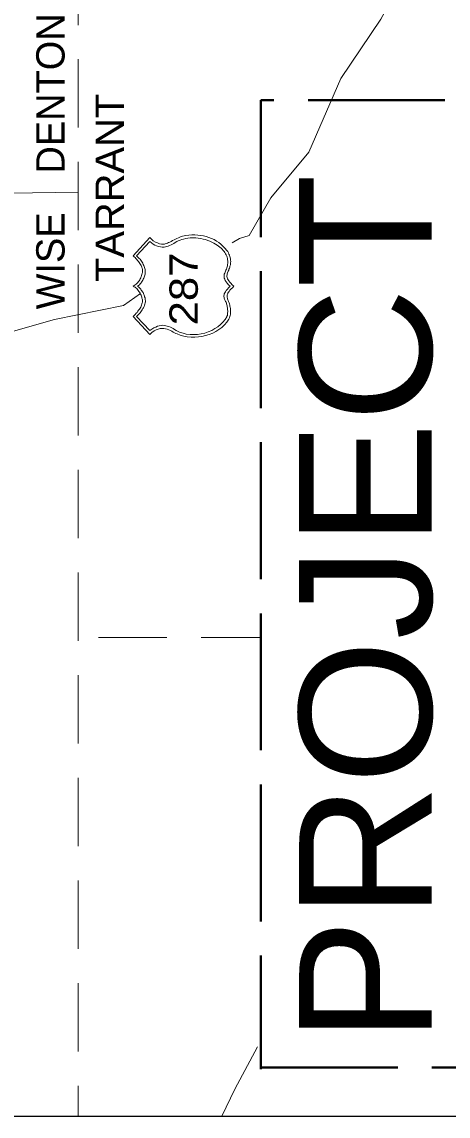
# Model space of a CAD drawing. Extents: x 2363323 to 2367082, y 6956018 to 6980837.
# Drawn here: x 2365838.7 to 2365915.4, y 6980386 to 6980582.6 of the extents above; entities that cross this region are included whole.
import ezdxf

# ---------------------------------------------------------------- set-up
doc = ezdxf.new("R2010")
doc.units = 0
doc.header["$LTSCALE"] = 4.1
doc.linetypes.add('LONG_DASHED', pattern=[7.5, 6, -1.5])
doc.linetypes.add('MEDIUM_DASHED', pattern=[4.5, 3, -1.5])
doc.layers.add('62', color=7, linetype='Continuous', lineweight=13)
doc.layers.add('63', color=7, linetype='Continuous', lineweight=13)

msp = doc.modelspace()

# ---------------------------------------------------------------- linework, layer by layer
at = {"layer": '62', "linetype": 'MEDIUM_DASHED'}
for p, q in [((2365848.822, 6980834.218), (2365848.821, 6980385.954)), ((2365848.822, 6980551.996), (2365753.976, 6980551.008)), ((2365852.512, 6980472.003), (2365881.718, 6980472.003))]:
    msp.add_line(p, q, dxfattribs=at)
at = {"layer": '62'}
for p, q in [((2365877.872, 6980543.694), (2365876.544, 6980542.906)), ((2365856.966, 6980531.656), (2365860.026, 6980533.816)), ((2365877.039, 6980390.817), (2365881.089, 6980398.377)), ((2365874.678, 6980385.954), (2365877.039, 6980390.817))]:
    msp.add_line(p, q, dxfattribs=at)
at = {"layer": '62', "lineweight": 25}
msp.add_lwpolyline([(2365753.976, 6980385.954), (2366219.249, 6980385.954), (2366219.249, 6980835.546), (2365753.974, 6980835.546)], dxfattribs=at)
at = {"layer": '62'}
for points in [[(2365877.872, 6980543.694), (2365879.582, 6980544.234), (2365883.498, 6980551.006), (2365890.316, 6980559.222), (2365896.098, 6980572.431), (2365903.3, 6980583.117), (2365906.968, 6980589.936)], [(2365861.714, 6980526.435), (2365858.698, 6980529.699), (2365858.902, 6980529.878), (2365859.104, 6980530.059), (2365859.262, 6980530.263), (2365859.441, 6980530.418), (2365859.574, 6980530.622), (2365859.711, 6980530.802), (2365859.846, 6980530.982), (2365859.981, 6980531.184), (2365860.094, 6980531.343), (2365860.161, 6980531.546), (2365860.251, 6980531.722), (2365860.296, 6980531.926), (2365860.364, 6980532.106), (2365860.408, 6980532.264), (2365860.408, 6980532.489), (2365860.386, 6980532.692), (2365860.364, 6980532.826), (2365860.296, 6980532.986), (2365860.275, 6980533.166), (2365860.23, 6980533.344), (2365860.138, 6980533.522), (2365860.071, 6980533.682), (2365859.981, 6980533.862), (2365859.891, 6980534.042), (2365859.756, 6980534.199), (2365859.644, 6980534.379), (2365859.488, 6980534.538), (2365859.374, 6980534.696), (2365859.216, 6980534.806), (2365859.06, 6980534.943), (2365858.878, 6980535.01), (2365858.698, 6980535.12), (2365858.878, 6980535.234), (2365859.06, 6980535.345), (2365859.238, 6980535.482), (2365859.374, 6980535.616), (2365859.554, 6980535.774), (2365859.666, 6980535.952), (2365859.802, 6980536.112), (2365859.914, 6980536.293), (2365860.004, 6980536.472), (2365860.118, 6980536.629), (2365860.184, 6980536.854), (2365860.251, 6980537.01), (2365860.296, 6980537.259), (2365860.365, 6980537.416), (2365860.408, 6980537.642), (2365860.408, 6980537.822), (2365860.41, 6980537.979), (2365860.41, 6980538.182), (2365860.341, 6980538.316), (2365860.296, 6980538.519), (2365860.206, 6980538.699), (2365860.14, 6980538.856), (2365860.026, 6980539.014), (2365859.914, 6980539.216), (2365859.801, 6980539.374), (2365859.666, 6980539.554), (2365859.532, 6980539.713), (2365859.374, 6980539.914), (2365859.216, 6980540.072), (2365859.058, 6980540.252), (2365858.878, 6980540.408), (2365858.698, 6980540.589), (2365861.714, 6980543.852), (2365862.008, 6980543.558), (2365862.345, 6980543.265), (2365862.726, 6980543.064), (2365863.107, 6980542.908), (2365863.491, 6980542.749), (2365863.851, 6980542.683), (2365864.144, 6980542.682), (2365864.346, 6980542.682), (2365864.504, 6980542.726), (2365864.708, 6980542.794), (2365864.886, 6980542.862), (2365865.112, 6980542.952), (2365865.338, 6980543.062), (2365865.561, 6980543.176), (2365865.808, 6980543.313), (2365866.078, 6980543.446), (2365866.328, 6980543.582), (2365866.575, 6980543.716), (2365866.866, 6980543.829), (2365867.114, 6980543.942), (2365867.384, 6980544.033), (2365867.631, 6980544.122), (2365867.88, 6980544.189), (2365868.126, 6980544.234), (2365868.711, 6980544.302), (2365869.274, 6980544.369), (2365869.792, 6980544.369), (2365870.334, 6980544.302), (2365870.853, 6980544.258), (2365871.369, 6980544.166), (2365871.864, 6980544.032), (2365872.359, 6980543.874), (2365872.833, 6980543.716), (2365873.282, 6980543.49)], [(2365874.069, 6980542.299), (2365873.822, 6980542.502), (2365873.53, 6980542.68), (2365873.216, 6980542.862), (2365872.876, 6980543.043), (2365872.516, 6980543.199), (2365872.134, 6980543.356), (2365871.729, 6980543.49), (2365871.322, 6980543.604), (2365870.874, 6980543.716), (2365870.422, 6980543.763), (2365869.972, 6980543.83), (2365869.478, 6980543.829), (2365869.004, 6980543.806), (2365868.555, 6980543.762), (2365868.172, 6980543.716), (2365867.811, 6980543.604), (2365867.474, 6980543.514), (2365867.16, 6980543.38), (2365866.844, 6980543.266), (2365866.574, 6980543.132), (2365866.304, 6980542.974), (2365866.034, 6980542.816), (2365865.788, 6980542.683), (2365865.538, 6980542.569), (2365865.291, 6980542.456), (2365865.042, 6980542.344), (2365864.796, 6980542.276), (2365864.571, 6980542.21), (2365864.301, 6980542.164), (2365863.965, 6980542.142), (2365863.626, 6980542.209), (2365863.288, 6980542.278), (2365862.951, 6980542.366), (2365862.615, 6980542.502), (2365862.298, 6980542.683), (2365862.004, 6980542.906), (2365861.714, 6980543.132), (2365859.328, 6980540.565), (2365859.488, 6980540.409), (2365859.644, 6980540.272), (2365859.824, 6980540.116), (2365859.96, 6980539.959), (2365860.095, 6980539.779), (2365860.23, 6980539.599), (2365860.341, 6980539.419), (2365860.455, 6980539.24), (2365860.544, 6980539.038), (2365860.656, 6980538.856), (2365860.724, 6980538.654), (2365860.792, 6980538.472), (2365860.836, 6980538.294), (2365860.86, 6980538.136), (2365860.905, 6980537.979), (2365860.904, 6980537.823), (2365860.905, 6980537.664), (2365860.882, 6980537.484), (2365860.858, 6980537.282), (2365860.838, 6980537.124), (2365860.768, 6980536.899), (2365860.702, 6980536.742), (2365860.634, 6980536.563), (2365860.544, 6980536.359), (2365860.455, 6980536.203), (2365860.365, 6980535.999), (2365860.251, 6980535.864), (2365860.138, 6980535.708), (2365860.004, 6980535.525), (2365859.846, 6980535.39), (2365859.711, 6980535.256), (2365859.507, 6980535.122), (2365859.69, 6980534.986), (2365859.846, 6980534.852), (2365859.982, 6980534.716), (2365860.094, 6980534.582), (2365860.184, 6980534.424), (2365860.294, 6980534.312), (2365860.41, 6980534.133), (2365860.521, 6980533.996), (2365860.568, 6980533.839), (2365860.658, 6980533.659), (2365860.701, 6980533.524), (2365860.77, 6980533.344), (2365860.791, 6980533.186), (2365860.86, 6980533.03), (2365860.881, 6980532.849), (2365860.905, 6980532.692), (2365860.928, 6980532.536), (2365860.928, 6980532.309), (2365860.881, 6980532.108), (2365860.836, 6980531.883), (2365860.768, 6980531.702), (2365860.68, 6980531.476), (2365860.59, 6980531.25), (2365860.476, 6980531.096), (2365860.365, 6980530.869), (2365860.251, 6980530.668), (2365860.116, 6980530.486), (2365859.96, 6980530.329), (2365859.825, 6980530.126), (2365859.644, 6980529.97)], [(2365859.352, 6980529.698), (2365861.715, 6980527.132), (2365862.074, 6980527.402), (2365862.456, 6980527.628), (2365862.794, 6980527.785), (2365863.11, 6980527.942), (2365863.424, 6980528.01), (2365863.74, 6980528.078), (2365864.008, 6980528.1), (2365864.302, 6980528.078), (2365864.595, 6980528.01), (2365864.865, 6980527.966), (2365865.156, 6980527.876), (2365865.426, 6980527.742), (2365865.674, 6980527.628), (2365865.944, 6980527.494), (2365866.191, 6980527.335), (2365866.462, 6980527.178), (2365867.046, 6980526.886), (2365867.698, 6980526.682), (2365868.284, 6980526.526), (2365868.958, 6980526.459), (2365869.635, 6980526.435), (2365870.288, 6980526.458), (2365870.966, 6980526.57), (2365871.594, 6980526.705), (2365872.246, 6980526.908), (2365872.856, 6980527.178), (2365873.439, 6980527.494), (2365873.979, 6980527.828), (2365874.429, 6980528.236), (2365874.879, 6980528.662), (2365875.262, 6980529.135), (2365875.576, 6980529.609), (2365875.6, 6980529.722), (2365875.668, 6980529.858), (2365875.689, 6980530.014), (2365875.69, 6980530.194), (2365875.712, 6980530.329), (2365875.736, 6980530.509), (2365875.736, 6980530.689), (2365875.712, 6980530.868), (2365875.689, 6980531.072), (2365875.69, 6980531.229), (2365875.646, 6980531.432), (2365875.622, 6980531.612), (2365875.599, 6980531.769), (2365875.533, 6980531.95), (2365875.488, 6980532.106), (2365875.442, 6980532.243), (2365875.352, 6980532.376), (2365875.286, 6980532.534), (2365875.218, 6980532.648), (2365875.149, 6980532.804), (2365875.106, 6980532.962), (2365875.082, 6980533.096), (2365875.059, 6980533.254), (2365875.059, 6980533.412), (2365875.083, 6980533.569), (2365875.126, 6980533.772), (2365875.194, 6980533.952), (2365875.329, 6980534.132), (2365875.443, 6980534.356), (2365875.668, 6980534.582), (2365875.893, 6980534.852), (2365876.186, 6980535.099), (2365875.87, 6980535.392), (2365875.646, 6980535.662), (2365875.443, 6980535.909), (2365875.286, 6980536.155), (2365875.194, 6980536.359), (2365875.126, 6980536.562), (2365875.082, 6980536.742), (2365875.082, 6980536.966), (2365875.106, 6980537.124), (2365875.126, 6980537.283), (2365875.196, 6980537.484), (2365875.262, 6980537.664), (2365875.329, 6980537.822), (2365875.42, 6980538.003), (2365875.488, 6980538.204), (2365875.578, 6980538.406), (2365875.623, 6980538.609), (2365875.689, 6980538.812), (2365875.712, 6980539.014), (2365875.734, 6980539.239), (2365875.758, 6980539.442), (2365875.734, 6980539.665), (2365875.712, 6980539.869), (2365875.689, 6980540.094), (2365875.622, 6980540.32), (2365875.578, 6980540.522), (2365875.442, 6980540.746), (2365875.352, 6980540.949), (2365875.216, 6980541.152), (2365875.082, 6980541.376), (2365874.902, 6980541.556), (2365874.723, 6980541.759), (2365874.543, 6980541.939), (2365874.294, 6980542.119), (2365874.069, 6980542.299)], [(2365873.282, 6980543.49), (2365873.709, 6980543.244), (2365874.114, 6980542.952), (2365874.519, 6980542.68), (2365874.879, 6980542.299), (2365875.24, 6980541.962), (2365875.576, 6980541.556), (2365875.734, 6980541.332), (2365875.869, 6980541.128), (2365875.959, 6980540.904), (2365876.05, 6980540.679), (2365876.14, 6980540.478), (2365876.186, 6980540.252), (2365876.229, 6980540.004), (2365876.253, 6980539.803), (2365876.276, 6980539.554), (2365876.252, 6980539.328), (2365876.229, 6980539.126), (2365876.206, 6980538.945), (2365876.14, 6980538.723), (2365876.116, 6980538.542), (2365876.05, 6980538.36), (2365875.96, 6980538.182), (2365875.914, 6980538.002), (2365875.846, 6980537.822), (2365875.756, 6980537.685), (2365875.689, 6980537.506), (2365875.666, 6980537.373), (2365875.623, 6980537.192), (2365875.6, 6980537.01), (2365875.6, 6980536.856), (2365875.644, 6980536.674), (2365875.712, 6980536.472), (2365875.824, 6980536.293), (2365875.936, 6980536.09), (2365876.116, 6980535.866), (2365876.298, 6980535.639), (2365876.565, 6980535.392), (2365876.859, 6980535.123), (2365876.589, 6980534.852), (2365876.364, 6980534.628), (2365876.14, 6980534.424), (2365876.004, 6980534.199), (2365875.869, 6980534.04), (2365875.756, 6980533.862), (2365875.689, 6980533.704), (2365875.646, 6980533.546), (2365875.622, 6980533.412), (2365875.623, 6980533.254), (2365875.644, 6980533.12), (2365875.69, 6980532.962), (2365875.712, 6980532.849), (2365875.756, 6980532.693), (2365875.824, 6980532.534), (2365875.87, 6980532.399), (2365875.936, 6980532.264), (2365875.982, 6980532.106), (2365876.05, 6980531.926), (2365876.116, 6980531.726), (2365876.139, 6980531.546), (2365876.184, 6980531.343), (2365876.229, 6980531.138), (2365876.252, 6980530.958), (2365876.252, 6980530.736), (2365876.252, 6980530.532), (2365876.252, 6980530.329), (2365876.229, 6980530.08), (2365876.162, 6980529.879), (2365876.118, 6980529.654), (2365876.026, 6980529.426), (2365875.916, 6980529.202), (2365875.576, 6980528.686), (2365875.15, 6980528.19), (2365874.678, 6980527.718), (2365874.159, 6980527.335), (2365873.596, 6980526.975), (2365873.034, 6980526.681), (2365872.406, 6980526.459), (2365871.753, 6980526.255), (2365871.099, 6980526.098), (2365870.468, 6980526.008), (2365869.794, 6980525.962), (2365869.14, 6980525.962), (2365868.464, 6980526.03), (2365867.856, 6980526.141), (2365867.205, 6980526.322), (2365866.642, 6980526.549), (2365866.416, 6980526.638), (2365866.191, 6980526.75), (2365865.944, 6980526.886), (2365865.698, 6980527.02), (2365865.426, 6980527.155), (2365865.158, 6980527.292), (2365864.864, 6980527.401), (2365864.571, 6980527.47), (2365864.256, 6980527.539), (2365863.92, 6980527.538), (2365863.605, 6980527.515), (2365863.244, 6980527.425), (2365862.884, 6980527.288), (2365862.478, 6980527.088)], [(2365753.974, 6980486.178), (2365760.05, 6980491.737), (2365771.955, 6980498.895), (2365785.095, 6980504.764), (2365799.742, 6980507.016), (2365808.048, 6980507.691), (2365817.97, 6980511.358), (2365826.498, 6980519.638), (2365834.6, 6980526.3), (2365844.567, 6980529.112), (2365856.966, 6980531.656)], [(2365859.644, 6980529.97), (2365859.486, 6980529.834), (2365859.352, 6980529.698)], [(2365862.478, 6980527.088), (2365862.096, 6980526.818), (2365861.714, 6980526.435)]]:
    msp.add_lwpolyline(points, dxfattribs=at)
at = {"layer": '62', "linetype": 'LONG_DASHED', "lineweight": 40}
msp.add_lwpolyline([(2365881.719, 6980394.71), (2365945.535, 6980394.708), (2365945.535, 6980568.56), (2365881.72, 6980568.56), (2365881.719, 6980394.393)], dxfattribs=at)
at = {"layer": '63', "linetype": 'MEDIUM_DASHED'}
for p, q in [((2365848.822, 6980834.218), (2365848.821, 6980385.954)), ((2365848.822, 6980551.996), (2365753.976, 6980551.008)), ((2365852.512, 6980472.003), (2365881.718, 6980472.003))]:
    msp.add_line(p, q, dxfattribs=at)
at = {"layer": '63'}
for p, q in [((2365877.872, 6980543.694), (2365876.544, 6980542.906)), ((2365856.966, 6980531.656), (2365860.026, 6980533.816)), ((2365877.039, 6980390.817), (2365881.089, 6980398.377)), ((2365874.678, 6980385.954), (2365877.039, 6980390.817))]:
    msp.add_line(p, q, dxfattribs=at)
at = {"layer": '63', "lineweight": 25}
msp.add_lwpolyline([(2365753.976, 6980385.954), (2366219.249, 6980385.954), (2366219.249, 6980835.546), (2365753.974, 6980835.546)], dxfattribs=at)
at = {"layer": '63'}
for points in [[(2365877.872, 6980543.694), (2365879.582, 6980544.234), (2365883.498, 6980551.006), (2365890.316, 6980559.222), (2365896.098, 6980572.431), (2365903.3, 6980583.117), (2365906.968, 6980589.936)], [(2365861.714, 6980526.435), (2365858.698, 6980529.699), (2365858.902, 6980529.878), (2365859.104, 6980530.059), (2365859.262, 6980530.263), (2365859.441, 6980530.418), (2365859.574, 6980530.622), (2365859.711, 6980530.802), (2365859.846, 6980530.982), (2365859.981, 6980531.184), (2365860.094, 6980531.343), (2365860.161, 6980531.546), (2365860.251, 6980531.722), (2365860.296, 6980531.926), (2365860.364, 6980532.106), (2365860.408, 6980532.264), (2365860.408, 6980532.489), (2365860.386, 6980532.692), (2365860.364, 6980532.826), (2365860.296, 6980532.986), (2365860.275, 6980533.166), (2365860.23, 6980533.344), (2365860.138, 6980533.522), (2365860.071, 6980533.682), (2365859.981, 6980533.862), (2365859.891, 6980534.042), (2365859.756, 6980534.199), (2365859.644, 6980534.379), (2365859.488, 6980534.538), (2365859.374, 6980534.696), (2365859.216, 6980534.806), (2365859.06, 6980534.943), (2365858.878, 6980535.01), (2365858.698, 6980535.12), (2365858.878, 6980535.234), (2365859.06, 6980535.345), (2365859.238, 6980535.482), (2365859.374, 6980535.616), (2365859.554, 6980535.774), (2365859.666, 6980535.952), (2365859.802, 6980536.112), (2365859.914, 6980536.293), (2365860.004, 6980536.472), (2365860.118, 6980536.629), (2365860.184, 6980536.854), (2365860.251, 6980537.01), (2365860.296, 6980537.259), (2365860.365, 6980537.416), (2365860.408, 6980537.642), (2365860.408, 6980537.822), (2365860.41, 6980537.979), (2365860.41, 6980538.182), (2365860.341, 6980538.316), (2365860.296, 6980538.519), (2365860.206, 6980538.699), (2365860.14, 6980538.856), (2365860.026, 6980539.014), (2365859.914, 6980539.216), (2365859.801, 6980539.374), (2365859.666, 6980539.554), (2365859.532, 6980539.713), (2365859.374, 6980539.914), (2365859.216, 6980540.072), (2365859.058, 6980540.252), (2365858.878, 6980540.408), (2365858.698, 6980540.589), (2365861.714, 6980543.852), (2365862.008, 6980543.558), (2365862.345, 6980543.265), (2365862.726, 6980543.064), (2365863.107, 6980542.908), (2365863.491, 6980542.749), (2365863.851, 6980542.683), (2365864.144, 6980542.682), (2365864.346, 6980542.682), (2365864.504, 6980542.726), (2365864.708, 6980542.794), (2365864.886, 6980542.862), (2365865.112, 6980542.952), (2365865.338, 6980543.062), (2365865.561, 6980543.176), (2365865.808, 6980543.313), (2365866.078, 6980543.446), (2365866.328, 6980543.582), (2365866.575, 6980543.716), (2365866.866, 6980543.829), (2365867.114, 6980543.942), (2365867.384, 6980544.033), (2365867.631, 6980544.122), (2365867.88, 6980544.189), (2365868.126, 6980544.234), (2365868.711, 6980544.302), (2365869.274, 6980544.369), (2365869.792, 6980544.369), (2365870.334, 6980544.302), (2365870.853, 6980544.258), (2365871.369, 6980544.166), (2365871.864, 6980544.032), (2365872.359, 6980543.874), (2365872.833, 6980543.716), (2365873.282, 6980543.49)], [(2365874.069, 6980542.299), (2365873.822, 6980542.502), (2365873.53, 6980542.68), (2365873.216, 6980542.862), (2365872.876, 6980543.043), (2365872.516, 6980543.199), (2365872.134, 6980543.356), (2365871.729, 6980543.49), (2365871.322, 6980543.604), (2365870.874, 6980543.716), (2365870.422, 6980543.763), (2365869.972, 6980543.83), (2365869.478, 6980543.829), (2365869.004, 6980543.806), (2365868.555, 6980543.762), (2365868.172, 6980543.716), (2365867.811, 6980543.604), (2365867.474, 6980543.514), (2365867.16, 6980543.38), (2365866.844, 6980543.266), (2365866.574, 6980543.132), (2365866.304, 6980542.974), (2365866.034, 6980542.816), (2365865.788, 6980542.683), (2365865.538, 6980542.569), (2365865.291, 6980542.456), (2365865.042, 6980542.344), (2365864.796, 6980542.276), (2365864.571, 6980542.21), (2365864.301, 6980542.164), (2365863.965, 6980542.142), (2365863.626, 6980542.209), (2365863.288, 6980542.278), (2365862.951, 6980542.366), (2365862.615, 6980542.502), (2365862.298, 6980542.683), (2365862.004, 6980542.906), (2365861.714, 6980543.132), (2365859.328, 6980540.565), (2365859.488, 6980540.409), (2365859.644, 6980540.272), (2365859.824, 6980540.116), (2365859.96, 6980539.959), (2365860.095, 6980539.779), (2365860.23, 6980539.599), (2365860.341, 6980539.419), (2365860.455, 6980539.24), (2365860.544, 6980539.038), (2365860.656, 6980538.856), (2365860.724, 6980538.654), (2365860.792, 6980538.472), (2365860.836, 6980538.294), (2365860.86, 6980538.136), (2365860.905, 6980537.979), (2365860.904, 6980537.823), (2365860.905, 6980537.664), (2365860.882, 6980537.484), (2365860.858, 6980537.282), (2365860.838, 6980537.124), (2365860.768, 6980536.899), (2365860.702, 6980536.742), (2365860.634, 6980536.563), (2365860.544, 6980536.359), (2365860.455, 6980536.203), (2365860.365, 6980535.999), (2365860.251, 6980535.864), (2365860.138, 6980535.708), (2365860.004, 6980535.525), (2365859.846, 6980535.39), (2365859.711, 6980535.256), (2365859.507, 6980535.122), (2365859.69, 6980534.986), (2365859.846, 6980534.852), (2365859.982, 6980534.716), (2365860.094, 6980534.582), (2365860.184, 6980534.424), (2365860.294, 6980534.312), (2365860.41, 6980534.133), (2365860.521, 6980533.996), (2365860.568, 6980533.839), (2365860.658, 6980533.659), (2365860.701, 6980533.524), (2365860.77, 6980533.344), (2365860.791, 6980533.186), (2365860.86, 6980533.03), (2365860.881, 6980532.849), (2365860.905, 6980532.692), (2365860.928, 6980532.536), (2365860.928, 6980532.309), (2365860.881, 6980532.108), (2365860.836, 6980531.883), (2365860.768, 6980531.702), (2365860.68, 6980531.476), (2365860.59, 6980531.25), (2365860.476, 6980531.096), (2365860.365, 6980530.869), (2365860.251, 6980530.668), (2365860.116, 6980530.486), (2365859.96, 6980530.329), (2365859.825, 6980530.126), (2365859.644, 6980529.97)], [(2365859.352, 6980529.698), (2365861.715, 6980527.132), (2365862.074, 6980527.402), (2365862.456, 6980527.628), (2365862.794, 6980527.785), (2365863.11, 6980527.942), (2365863.424, 6980528.01), (2365863.74, 6980528.078), (2365864.008, 6980528.1), (2365864.302, 6980528.078), (2365864.595, 6980528.01), (2365864.865, 6980527.966), (2365865.156, 6980527.876), (2365865.426, 6980527.742), (2365865.674, 6980527.628), (2365865.944, 6980527.494), (2365866.191, 6980527.335), (2365866.462, 6980527.178), (2365867.046, 6980526.886), (2365867.698, 6980526.682), (2365868.284, 6980526.526), (2365868.958, 6980526.459), (2365869.635, 6980526.435), (2365870.288, 6980526.458), (2365870.966, 6980526.57), (2365871.594, 6980526.705), (2365872.246, 6980526.908), (2365872.856, 6980527.178), (2365873.439, 6980527.494), (2365873.979, 6980527.828), (2365874.429, 6980528.236), (2365874.879, 6980528.662), (2365875.262, 6980529.135), (2365875.576, 6980529.609), (2365875.6, 6980529.722), (2365875.668, 6980529.858), (2365875.689, 6980530.014), (2365875.69, 6980530.194), (2365875.712, 6980530.329), (2365875.736, 6980530.509), (2365875.736, 6980530.689), (2365875.712, 6980530.868), (2365875.689, 6980531.072), (2365875.69, 6980531.229), (2365875.646, 6980531.432), (2365875.622, 6980531.612), (2365875.599, 6980531.769), (2365875.533, 6980531.95), (2365875.488, 6980532.106), (2365875.442, 6980532.243), (2365875.352, 6980532.376), (2365875.286, 6980532.534), (2365875.218, 6980532.648), (2365875.149, 6980532.804), (2365875.106, 6980532.962), (2365875.082, 6980533.096), (2365875.059, 6980533.254), (2365875.059, 6980533.412), (2365875.083, 6980533.569), (2365875.126, 6980533.772), (2365875.194, 6980533.952), (2365875.329, 6980534.132), (2365875.443, 6980534.356), (2365875.668, 6980534.582), (2365875.893, 6980534.852), (2365876.186, 6980535.099), (2365875.87, 6980535.392), (2365875.646, 6980535.662), (2365875.443, 6980535.909), (2365875.286, 6980536.155), (2365875.194, 6980536.359), (2365875.126, 6980536.562), (2365875.082, 6980536.742), (2365875.082, 6980536.966), (2365875.106, 6980537.124), (2365875.126, 6980537.283), (2365875.196, 6980537.484), (2365875.262, 6980537.664), (2365875.329, 6980537.822), (2365875.42, 6980538.003), (2365875.488, 6980538.204), (2365875.578, 6980538.406), (2365875.623, 6980538.609), (2365875.689, 6980538.812), (2365875.712, 6980539.014), (2365875.734, 6980539.239), (2365875.758, 6980539.442), (2365875.734, 6980539.665), (2365875.712, 6980539.869), (2365875.689, 6980540.094), (2365875.622, 6980540.32), (2365875.578, 6980540.522), (2365875.442, 6980540.746), (2365875.352, 6980540.949), (2365875.216, 6980541.152), (2365875.082, 6980541.376), (2365874.902, 6980541.556), (2365874.723, 6980541.759), (2365874.543, 6980541.939), (2365874.294, 6980542.119), (2365874.069, 6980542.299)], [(2365873.282, 6980543.49), (2365873.709, 6980543.244), (2365874.114, 6980542.952), (2365874.519, 6980542.68), (2365874.879, 6980542.299), (2365875.24, 6980541.962), (2365875.576, 6980541.556), (2365875.734, 6980541.332), (2365875.869, 6980541.128), (2365875.959, 6980540.904), (2365876.05, 6980540.679), (2365876.14, 6980540.478), (2365876.186, 6980540.252), (2365876.229, 6980540.004), (2365876.253, 6980539.803), (2365876.276, 6980539.554), (2365876.252, 6980539.328), (2365876.229, 6980539.126), (2365876.206, 6980538.945), (2365876.14, 6980538.723), (2365876.116, 6980538.542), (2365876.05, 6980538.36), (2365875.96, 6980538.182), (2365875.914, 6980538.002), (2365875.846, 6980537.822), (2365875.756, 6980537.685), (2365875.689, 6980537.506), (2365875.666, 6980537.373), (2365875.623, 6980537.192), (2365875.6, 6980537.01), (2365875.6, 6980536.856), (2365875.644, 6980536.674), (2365875.712, 6980536.472), (2365875.824, 6980536.293), (2365875.936, 6980536.09), (2365876.116, 6980535.866), (2365876.298, 6980535.639), (2365876.565, 6980535.392), (2365876.859, 6980535.123), (2365876.589, 6980534.852), (2365876.364, 6980534.628), (2365876.14, 6980534.424), (2365876.004, 6980534.199), (2365875.869, 6980534.04), (2365875.756, 6980533.862), (2365875.689, 6980533.704), (2365875.646, 6980533.546), (2365875.622, 6980533.412), (2365875.623, 6980533.254), (2365875.644, 6980533.12), (2365875.69, 6980532.962), (2365875.712, 6980532.849), (2365875.756, 6980532.693), (2365875.824, 6980532.534), (2365875.87, 6980532.399), (2365875.936, 6980532.264), (2365875.982, 6980532.106), (2365876.05, 6980531.926), (2365876.116, 6980531.726), (2365876.139, 6980531.546), (2365876.184, 6980531.343), (2365876.229, 6980531.138), (2365876.252, 6980530.958), (2365876.252, 6980530.736), (2365876.252, 6980530.532), (2365876.252, 6980530.329), (2365876.229, 6980530.08), (2365876.162, 6980529.879), (2365876.118, 6980529.654), (2365876.026, 6980529.426), (2365875.916, 6980529.202), (2365875.576, 6980528.686), (2365875.15, 6980528.19), (2365874.678, 6980527.718), (2365874.159, 6980527.335), (2365873.596, 6980526.975), (2365873.034, 6980526.681), (2365872.406, 6980526.459), (2365871.753, 6980526.255), (2365871.099, 6980526.098), (2365870.468, 6980526.008), (2365869.794, 6980525.962), (2365869.14, 6980525.962), (2365868.464, 6980526.03), (2365867.856, 6980526.141), (2365867.205, 6980526.322), (2365866.642, 6980526.549), (2365866.416, 6980526.638), (2365866.191, 6980526.75), (2365865.944, 6980526.886), (2365865.698, 6980527.02), (2365865.426, 6980527.155), (2365865.158, 6980527.292), (2365864.864, 6980527.401), (2365864.571, 6980527.47), (2365864.256, 6980527.539), (2365863.92, 6980527.538), (2365863.605, 6980527.515), (2365863.244, 6980527.425), (2365862.884, 6980527.288), (2365862.478, 6980527.088)], [(2365753.974, 6980486.178), (2365760.05, 6980491.737), (2365771.955, 6980498.895), (2365785.095, 6980504.764), (2365799.742, 6980507.016), (2365808.048, 6980507.691), (2365817.97, 6980511.358), (2365826.498, 6980519.638), (2365834.6, 6980526.3), (2365844.567, 6980529.112), (2365856.966, 6980531.656)], [(2365859.644, 6980529.97), (2365859.486, 6980529.834), (2365859.352, 6980529.698)], [(2365862.478, 6980527.088), (2365862.096, 6980526.818), (2365861.714, 6980526.435)]]:
    msp.add_lwpolyline(points, dxfattribs=at)
at = {"layer": '63', "linetype": 'LONG_DASHED', "lineweight": 40}
msp.add_lwpolyline([(2365881.719, 6980394.71), (2365945.535, 6980394.708), (2365945.535, 6980568.56), (2365881.72, 6980568.56), (2365881.719, 6980394.393)], dxfattribs=at)

# ---------------------------------------------------------------- texts
at = {"layer": '62'}
for s, p in [('DENTON', (2365846.391, 6980555.374)), ('WISE', (2365846.39, 6980530.959))]:
    msp.add_text(s, height=5.099, rotation=90, dxfattribs=at).set_placement(p)
for s, height, width, p in [('TARRANT', 5.099, 1.05, (2365857.057, 6980535.886)), ('PROJECT', 23.83, 1.05, (2365912.411, 6980399.097)), ('287', 5.099, 1.15, (2365870.354, 6980528.078))]:
    msp.add_text(s, height=height, rotation=90, dxfattribs=dict(at, width=width)).set_placement(p)
at = {"layer": '63'}
for s, p in [('DENTON', (2365846.391, 6980555.374)), ('WISE', (2365846.39, 6980530.959))]:
    msp.add_text(s, height=5.099, rotation=90, dxfattribs=at).set_placement(p)
for s, height, width, p in [('TARRANT', 5.099, 1.05, (2365857.057, 6980535.886)), ('PROJECT', 23.83, 1.05, (2365912.411, 6980399.097)), ('287', 5.099, 1.15, (2365870.354, 6980528.078))]:
    msp.add_text(s, height=height, rotation=90, dxfattribs=dict(at, width=width)).set_placement(p)

doc.saveas('drawing.dxf')
